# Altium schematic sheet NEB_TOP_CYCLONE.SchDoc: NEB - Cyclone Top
size A4; Organization: Altium Limited; Address1: L3, 12a Rodborough Rd; Address2: Frenchs Forest; Address3: NSW; Address4: Australia 2086; DocumentNumber: 1; SheetNumber: 1; SheetTotal: 10
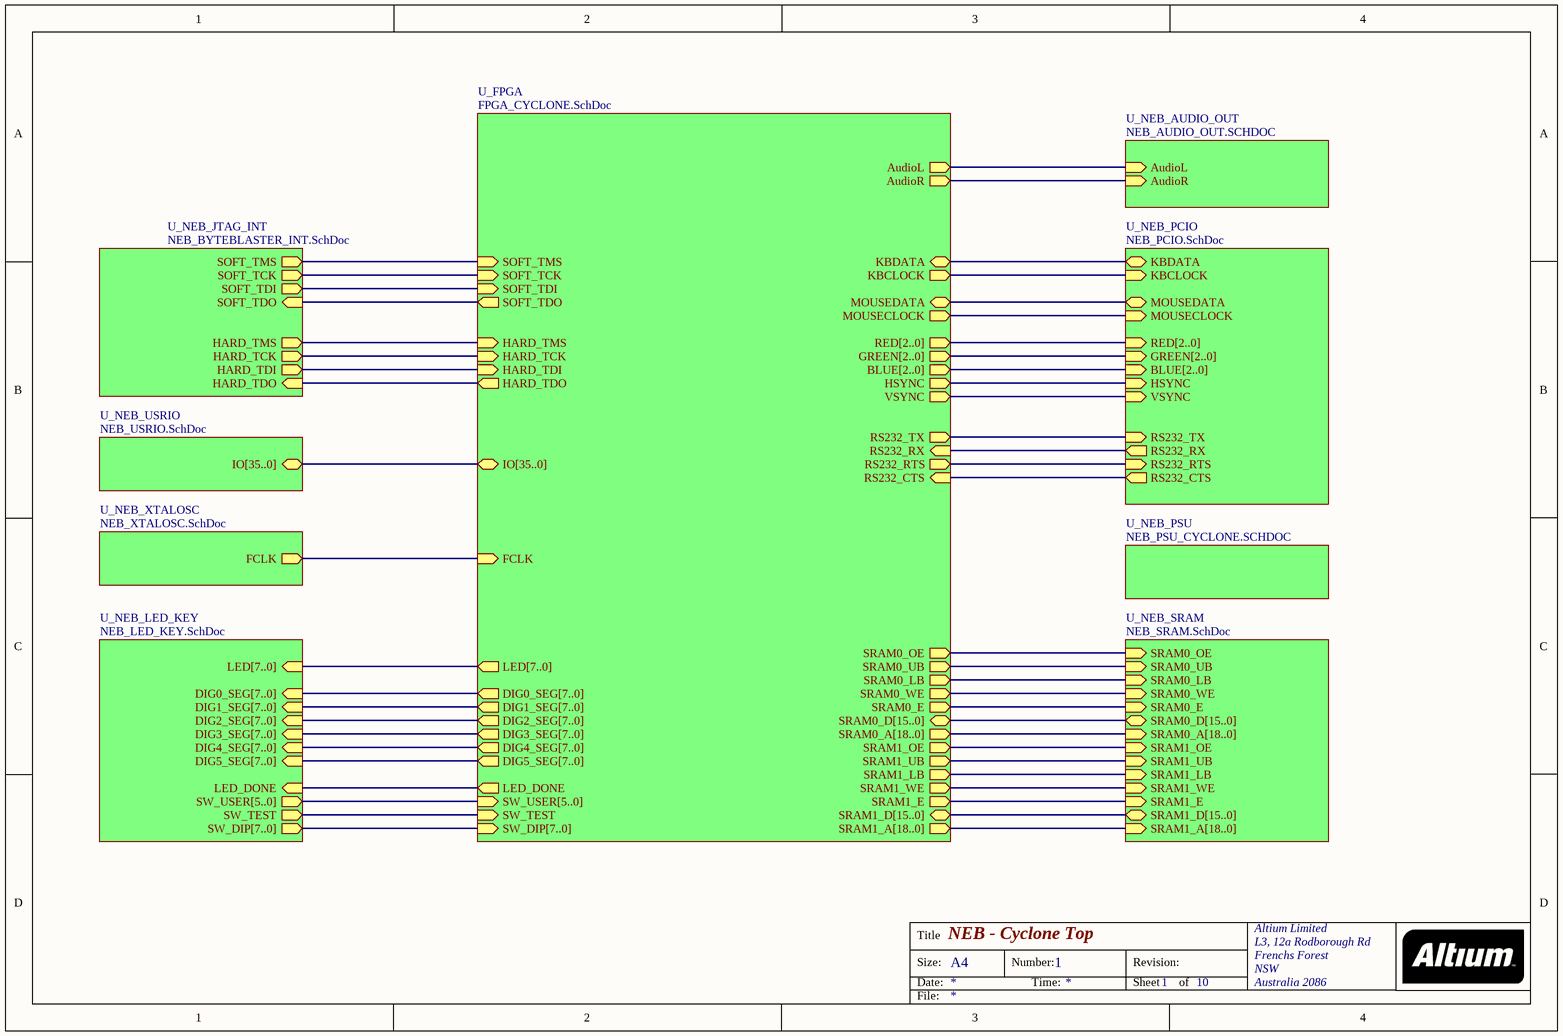
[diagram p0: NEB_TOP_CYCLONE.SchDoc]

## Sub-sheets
U_FPGA = FPGA_CYCLONE.SchDoc: SOFT_TMS (in), SOFT_TCK (in), SOFT_TDI (in), SOFT_TDO (out), HARD_TMS (in), HARD_TCK (in), HARD_TDI (in), HARD_TDO (out), IO[35..0] (bidir), FCLK (in), LED[7..0] (out), DIG1_SEG[7..0] (out), DIG0_SEG[7..0] (out), DIG2_SEG[7..0] (out), DIG3_SEG[7..0] (out), LED_DONE (out), SW_USER[5..0] (in), SRAM1_E (out), SRAM1_WE (out), SRAM1_LB (out), SRAM1_UB (out), SRAM1_OE (out), SRAM0_E (out), SRAM0_WE (out), SRAM0_LB (out), SRAM0_UB (out), SRAM0_OE (out), SRAM0_A[18..0] (out), SRAM1_A[18..0] (out), RS232_RTS (out), RS232_TX (out), VSYNC (out), HSYNC (out), BLUE[2..0] (out), GREEN[2..0] (out), RED[2..0] (out), MOUSECLOCK (out), KBCLOCK (out), AudioR (out), AudioL (out), SW_TEST (in), SW_DIP[7..0] (in), RS232_RX (in), RS232_CTS (in), KBDATA (bidir), MOUSEDATA (bidir), SRAM0_D[15..0] (bidir), SRAM1_D[15..0] (bidir), DIG4_SEG[7..0] (out), DIG5_SEG[7..0] (out)
U_NEB_AUDIO_OUT = NEB_AUDIO_OUT.SCHDOC: AudioL (in), AudioR (in)
U_NEB_JTAG_INT = NEB_BYTEBLASTER_INT.SchDoc: SOFT_TCK (out), SOFT_TDI (out), SOFT_TMS (out), SOFT_TDO (in), HARD_TMS (out), HARD_TCK (out), HARD_TDI (out), HARD_TDO (in)
U_NEB_LED_KEY = NEB_LED_KEY.SchDoc: LED[7..0] (in), SW_DIP[7..0] (out), DIG0_SEG[7..0] (in), DIG1_SEG[7..0] (in), DIG2_SEG[7..0] (in), DIG3_SEG[7..0] (in), SW_TEST (out), SW_USER[5..0] (out), LED_DONE (in), DIG4_SEG[7..0] (in), DIG5_SEG[7..0] (in)
U_NEB_PCIO = NEB_PCIO.SchDoc: RS232_RTS (in), RS232_TX (in), RS232_CTS (out), RS232_RX (out), KBDATA (bidir), KBCLOCK (in), MOUSEDATA (bidir), MOUSECLOCK (in), RED[2..0] (in), GREEN[2..0] (in), HSYNC (in), VSYNC (in), BLUE[2..0] (in)
U_NEB_PSU = NEB_PSU_CYCLONE.SCHDOC: no entries
U_NEB_SRAM = NEB_SRAM.SchDoc: SRAM0_OE (in), SRAM0_UB (in), SRAM0_LB (in), SRAM0_WE (in), SRAM0_E (in), SRAM0_D[15..0] (bidir), SRAM0_A[18..0] (in), SRAM1_OE (in), SRAM1_UB (in), SRAM1_LB (in), SRAM1_WE (in), SRAM1_E (in), SRAM1_D[15..0] (bidir), SRAM1_A[18..0] (in)
U_NEB_USRIO = NEB_USRIO.SchDoc: IO[35..0] (bidir)
U_NEB_XTALOSC = NEB_XTALOSC.SchDoc: FCLK (out)

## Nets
(unnamed): sheet U_NEB_JTAG_INT/SOFT_TCK, sheet U_FPGA/SOFT_TCK
(unnamed): sheet U_NEB_JTAG_INT/SOFT_TDI, sheet U_FPGA/SOFT_TDI  [a separate net that carries the same name]
(unnamed): sheet U_NEB_JTAG_INT/SOFT_TMS, sheet U_FPGA/SOFT_TMS  [a separate net that carries the same name]
(unnamed): sheet U_NEB_JTAG_INT/SOFT_TDO, sheet U_FPGA/SOFT_TDO  [a separate net that carries the same name]
(unnamed): sheet U_NEB_JTAG_INT/HARD_TMS, sheet U_FPGA/HARD_TMS  [a separate net that carries the same name]
(unnamed): sheet U_NEB_JTAG_INT/HARD_TCK, sheet U_FPGA/HARD_TCK  [a separate net that carries the same name]
(unnamed): sheet U_NEB_JTAG_INT/HARD_TDI, sheet U_FPGA/HARD_TDI  [a separate net that carries the same name]
(unnamed): sheet U_NEB_JTAG_INT/HARD_TDO, sheet U_FPGA/HARD_TDO  [a separate net that carries the same name]
(unnamed): sheet U_NEB_AUDIO_OUT/AudioL, sheet U_FPGA/AudioL  [a separate net that carries the same name]
(unnamed): sheet U_NEB_AUDIO_OUT/AudioR, sheet U_FPGA/AudioR  [a separate net that carries the same name]
(unnamed): sheet U_NEB_LED_KEY/SW_TEST, sheet U_FPGA/SW_TEST  [a separate net that carries the same name]
(unnamed): sheet U_NEB_LED_KEY/LED_DONE, sheet U_FPGA/LED_DONE  [a separate net that carries the same name]
(unnamed): sheet U_NEB_SRAM/SRAM0_OE, sheet U_FPGA/SRAM0_OE  [a separate net that carries the same name]
(unnamed): sheet U_NEB_SRAM/SRAM0_UB, sheet U_FPGA/SRAM0_UB  [a separate net that carries the same name]
(unnamed): sheet U_NEB_SRAM/SRAM0_LB, sheet U_FPGA/SRAM0_LB  [a separate net that carries the same name]
(unnamed): sheet U_NEB_SRAM/SRAM0_WE, sheet U_FPGA/SRAM0_WE  [a separate net that carries the same name]
(unnamed): sheet U_NEB_SRAM/SRAM0_E, sheet U_FPGA/SRAM0_E  [a separate net that carries the same name]
(unnamed): sheet U_NEB_SRAM/SRAM1_OE, sheet U_FPGA/SRAM1_OE  [a separate net that carries the same name]
(unnamed): sheet U_NEB_SRAM/SRAM1_UB, sheet U_FPGA/SRAM1_UB  [a separate net that carries the same name]
(unnamed): sheet U_NEB_SRAM/SRAM1_LB, sheet U_FPGA/SRAM1_LB  [a separate net that carries the same name]
(unnamed): sheet U_NEB_SRAM/SRAM1_WE, sheet U_FPGA/SRAM1_WE  [a separate net that carries the same name]
(unnamed): sheet U_NEB_SRAM/SRAM1_E, sheet U_FPGA/SRAM1_E  [a separate net that carries the same name]
(unnamed): sheet U_NEB_XTALOSC/FCLK, sheet U_FPGA/FCLK  [a separate net that carries the same name]
(unnamed): sheet U_NEB_PCIO/RS232_RTS, sheet U_FPGA/RS232_RTS  [a separate net that carries the same name]
(unnamed): sheet U_NEB_PCIO/RS232_TX, sheet U_FPGA/RS232_TX  [a separate net that carries the same name]
(unnamed): sheet U_NEB_PCIO/RS232_CTS, sheet U_FPGA/RS232_CTS  [a separate net that carries the same name]
(unnamed): sheet U_NEB_PCIO/RS232_RX, sheet U_FPGA/RS232_RX  [a separate net that carries the same name]
(unnamed): sheet U_NEB_PCIO/KBDATA, sheet U_FPGA/KBDATA  [a separate net that carries the same name]
(unnamed): sheet U_NEB_PCIO/KBCLOCK, sheet U_FPGA/KBCLOCK  [a separate net that carries the same name]
(unnamed): sheet U_NEB_PCIO/MOUSEDATA, sheet U_FPGA/MOUSEDATA  [a separate net that carries the same name]
(unnamed): sheet U_NEB_PCIO/MOUSECLOCK, sheet U_FPGA/MOUSECLOCK  [a separate net that carries the same name]
(unnamed): sheet U_NEB_PCIO/HSYNC, sheet U_FPGA/HSYNC  [a separate net that carries the same name]
(unnamed): sheet U_NEB_PCIO/VSYNC, sheet U_FPGA/VSYNC  [a separate net that carries the same name]

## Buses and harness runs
bus sheet U_FPGA/BLUE[2..0] = sheet U_NEB_PCIO/BLUE[2..0]
bus sheet U_FPGA/DIG0_SEG[7..0] = sheet U_NEB_LED_KEY/DIG0_SEG[7..0]
bus sheet U_FPGA/DIG1_SEG[7..0] = sheet U_NEB_LED_KEY/DIG1_SEG[7..0]
bus sheet U_FPGA/DIG2_SEG[7..0] = sheet U_NEB_LED_KEY/DIG2_SEG[7..0]
bus sheet U_FPGA/DIG3_SEG[7..0] = sheet U_NEB_LED_KEY/DIG3_SEG[7..0]
bus sheet U_FPGA/DIG4_SEG[7..0] = sheet U_NEB_LED_KEY/DIG4_SEG[7..0]
bus sheet U_FPGA/DIG5_SEG[7..0] = sheet U_NEB_LED_KEY/DIG5_SEG[7..0]
bus sheet U_FPGA/GREEN[2..0] = sheet U_NEB_PCIO/GREEN[2..0]
bus sheet U_FPGA/IO[35..0] = sheet U_NEB_USRIO/IO[35..0]
bus sheet U_FPGA/LED[7..0] = sheet U_NEB_LED_KEY/LED[7..0]
bus sheet U_FPGA/RED[2..0] = sheet U_NEB_PCIO/RED[2..0]
bus sheet U_FPGA/SRAM0_A[18..0] = sheet U_NEB_SRAM/SRAM0_A[18..0]
bus sheet U_FPGA/SRAM0_D[15..0] = sheet U_NEB_SRAM/SRAM0_D[15..0]
bus sheet U_FPGA/SRAM1_A[18..0] = sheet U_NEB_SRAM/SRAM1_A[18..0]
bus sheet U_FPGA/SRAM1_D[15..0] = sheet U_NEB_SRAM/SRAM1_D[15..0]
bus sheet U_FPGA/SW_DIP[7..0] = sheet U_NEB_LED_KEY/SW_DIP[7..0]
bus sheet U_FPGA/SW_USER[5..0] = sheet U_NEB_LED_KEY/SW_USER[5..0]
